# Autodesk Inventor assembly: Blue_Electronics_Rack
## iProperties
Shininess: 64.0
Length Units: 11272
Angle Units: 11279
Time Units: 11290
Mass Units: 11286
Length Display Precision: 3
Angle Display Precision: 2
Compacted: True
Part Number: Blue_Electronics_Rack
Document SubType Name: Assembly
Created: 2004-12
Designer: John Blackburn
Manufacturer: Standard
Standards Organization: Custom
Density: 0.0
Volumn: 0.0
Area: 0.0
PropertySet Name: Model Information
Control State: 0
Master: False
Checked Out: False
Author: John Blackburn
